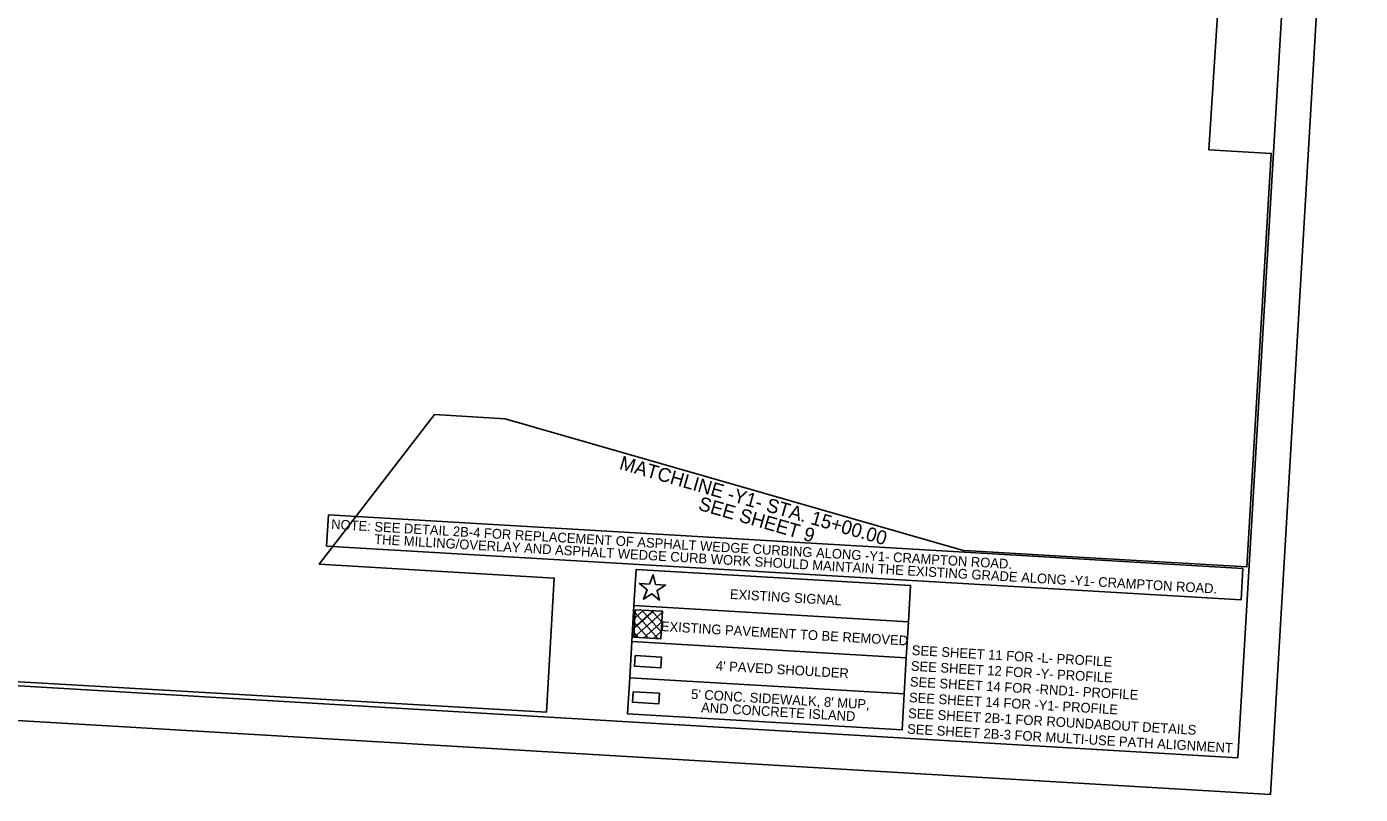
# Model space of a CAD drawing. Extents: x 2010810 to 2012732, y 444258 to 445456.
# Drawn here: x 2011771 to 2012732, y 444258 to 444812 of the extents above; entities that cross this region are included whole.
import ezdxf

# ---------------------------------------------------------------- set-up
doc = ezdxf.new("R2010")
doc.units = 0
for name, color, linetype in [('Exist PHM Road to be Removed Shape', 7, 'Continuous'), ('Matchline', 7, 'Continuous'), ('Matchline Text', 7, 'Continuous'), ('Old_Level_1', 7, 'Continuous'), ('Prop DSN Text', 7, 'Continuous'), ('Prop RDY Traffic Signal CELL', 7, 'Continuous'), ('Prop Shade Light', 7, 'Continuous'), ('Prop Shade Medium', 7, 'Continuous'), ('Scratch_Level_0', 7, 'Continuous'), ('Sheet Clip Boundary CELL', 7, 'Continuous'), ('Sheet Plan And Profile CELL', 7, 'Continuous'), ('Sheet Plot Border Outside CELL', 7, 'Continuous')]:
    doc.layers.add(name, color=color, linetype=linetype)

msp = doc.modelspace()

# ---------------------------------------------------------------- linework, layer by layer
at = {"layer": 'Exist PHM Road to be Removed Shape'}
for p, q in [((2012208.96, 444371.58), (2012229.35, 444389.69)), ((2012209, 444378.3), (2012222.84, 444390.6)), ((2012209.42, 444385.36), (2012215.79, 444391.02)), ((2012209.63, 444389.04), (2012226.05, 444370.57)), ((2012214.5, 444391.09), (2012228.5, 444375.33)), ((2012221.55, 444390.68), (2012228.92, 444382.39)), ((2012228.61, 444390.26), (2012229.33, 444389.45)), ((2012209.22, 444381.98), (2012218.99, 444370.98)), ((2012216.02, 444371.16), (2012228.93, 444382.63)), ((2012208.8, 444374.92), (2012211.93, 444371.4)), ((2012223.08, 444370.74), (2012228.52, 444375.58))]:
    msp.add_line(p, q, dxfattribs=at)
msp.add_lwpolyline([(2012209.77, 444391.37), (2012229.38, 444390.22), (2012228.21, 444370.44), (2012208.6, 444371.6)], close=True, dxfattribs=at)
at = {"layer": 'Matchline'}
msp.add_line((2012116.09, 444528.98), (2012447, 444433.71), dxfattribs=at)
at = {"layer": 'Old_Level_1'}
for p, q in [((2012207.25, 444368.35), (2012205.71, 444342.34)), ((2012405.1, 444356.69), (2012403.56, 444330.67))]:
    msp.add_line(p, q, dxfattribs=at)
for points in [[(2011988.56, 444459.83), (2012647.77, 444420.97), (2012646.43, 444398.38), (2011987.23, 444437.24)], [(2012210.31, 444420.38), (2012408.16, 444408.72), (2012406.63, 444382.7), (2012208.78, 444394.36)], [(2012208.78, 444394.36), (2012406.63, 444382.7), (2012405.1, 444356.69), (2012207.25, 444368.35)], [(2012205.71, 444342.34), (2012403.56, 444330.67), (2012402.03, 444304.66), (2012204.18, 444316.32)]]:
    msp.add_lwpolyline(points, close=True, dxfattribs=at)
at = {"layer": 'Prop RDY Traffic Signal CELL'}
msp.add_lwpolyline([(2012219.91, 444409.83), (2012212.71, 444410.25), (2012218.28, 444405.68), (2012215.65, 444398.96), (2012221.74, 444402.85), (2012227.32, 444398.27), (2012225.49, 444405.26), (2012231.57, 444409.15), (2012224.36, 444409.57), (2012222.54, 444416.56), (2012219.91, 444409.83)], dxfattribs=at)
at = {"layer": 'Prop Shade Light'}
msp.add_lwpolyline([(2012209.64, 444358.22), (2012228.66, 444357.1), (2012228.21, 444349.49), (2012209.19, 444350.62)], close=True, dxfattribs=at)
at = {"layer": 'Prop Shade Medium'}
msp.add_lwpolyline([(2012208.11, 444332.21), (2012227.12, 444331.09), (2012226.67, 444323.48), (2012207.66, 444324.6)], close=True, dxfattribs=at)
at = {"layer": 'Scratch_Level_0'}
msp.add_line((2012623.18, 444722.98), (2012668.12, 444720.33), dxfattribs=at)
at = {"layer": 'Sheet Clip Boundary CELL'}
msp.add_lwpolyline([(2011147.85, 444375), (2012145.7, 444317.47), (2012151.4, 444414.1), (2011981.99, 444424.08), (2012065.05, 444531.98), (2012116.09, 444528.98), (2012447, 444433.71), (2012447.13, 444434.15), (2012512.37, 444430.3), (2012650.61, 444422.16), (2012668.12, 444720.33), (2012623.18, 444722.98), (2012629.52, 444823.68), (2012643.65, 445063.27), (2012648.58, 445153.9), (2012495.5, 445162.92), (2012502.28, 445278.05), (2012302.58, 445289.82), (2012278.52, 445262.33), (2012176.97, 445268.45), (2011765.99, 445293.2), (2011771.61, 445387.92), (2011477.93, 445405.24)], dxfattribs=at)
at = {"layer": 'Sheet Plan And Profile CELL'}
msp.add_lwpolyline([(2012705.91, 445332.85), (2011208.51, 445421.12), (2011146.72, 444372.94), (2012644.12, 444284.67)], close=True, dxfattribs=at)
at = {"layer": 'Sheet Plot Border Outside CELL'}
msp.add_lwpolyline([(2010970.55, 444358.28), (2012667.61, 444258.24), (2012732.34, 445356.33), (2011035.28, 445456.37)], close=True, dxfattribs=at)

# ---------------------------------------------------------------- texts
at = {"layer": 'Matchline Text'}
for s, p in [('MATCHLINE -Y1- STA. 15+00.00', (2012197.67, 444492.91)), ('SEE SHEET 9', (2012254.52, 444463.53))]:
    msp.add_text(s, height=10, rotation=343.94025, dxfattribs=at).set_placement(p)
at = {"layer": 'Prop DSN Text'}
for s, p in [('NOTE: SEE DETAIL 2B-4 FOR REPLACEMENT OF ASPHALT WEDGE CURBING ALONG -Y1- CRAMPTON ROAD.', (2011990.4, 444449.66)), ('THE MILLING/OVERLAY AND ASPHALT WEDGE CURB WORK SHOULD MAINTAIN THE EXISTING GRADE ALONG -Y1- CRAMPTON ROAD.', (2012021.45, 444438.77)), ('EXISTING SIGNAL', (2012277.82, 444399.18)), ('EXISTING PAVEMENT TO BE REMOVED', (2012228.06, 444376.01)), ('SEE SHEET 11 FOR -L- PROFILE', (2012408.88, 444358.77)), ("4' PAVED SHOULDER", (2012267.66, 444347.57)), ('SEE SHEET 12 FOR -Y- PROFILE', (2012408.22, 444347.41)), ('SEE SHEET 14 FOR -RND1- PROFILE', (2012407.55, 444336.06)), ("5' CONC. SIDEWALK, 8' MUP,", (2012249.78, 444327.11)), ('SEE SHEET 14 FOR -Y1- PROFILE', (2012406.88, 444324.7)), ('AND CONCRETE ISLAND', (2012257.07, 444317.49)), ('SEE SHEET 2B-1 FOR ROUNDABOUT DETAILS', (2012406.21, 444313.34)), ('SEE SHEET 2B-3 FOR MULTI-USE PATH ALIGNMENT', (2012405.54, 444301.99))]:
    msp.add_text(s, height=7, rotation=356.62643, dxfattribs=at).set_placement(p)

doc.saveas('drawing.dxf')
